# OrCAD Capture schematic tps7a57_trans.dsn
size A; title: TPS7A57 5-A, Low-VIN Ultra-Low Dropout Voltage Regulator; rev: 1.0
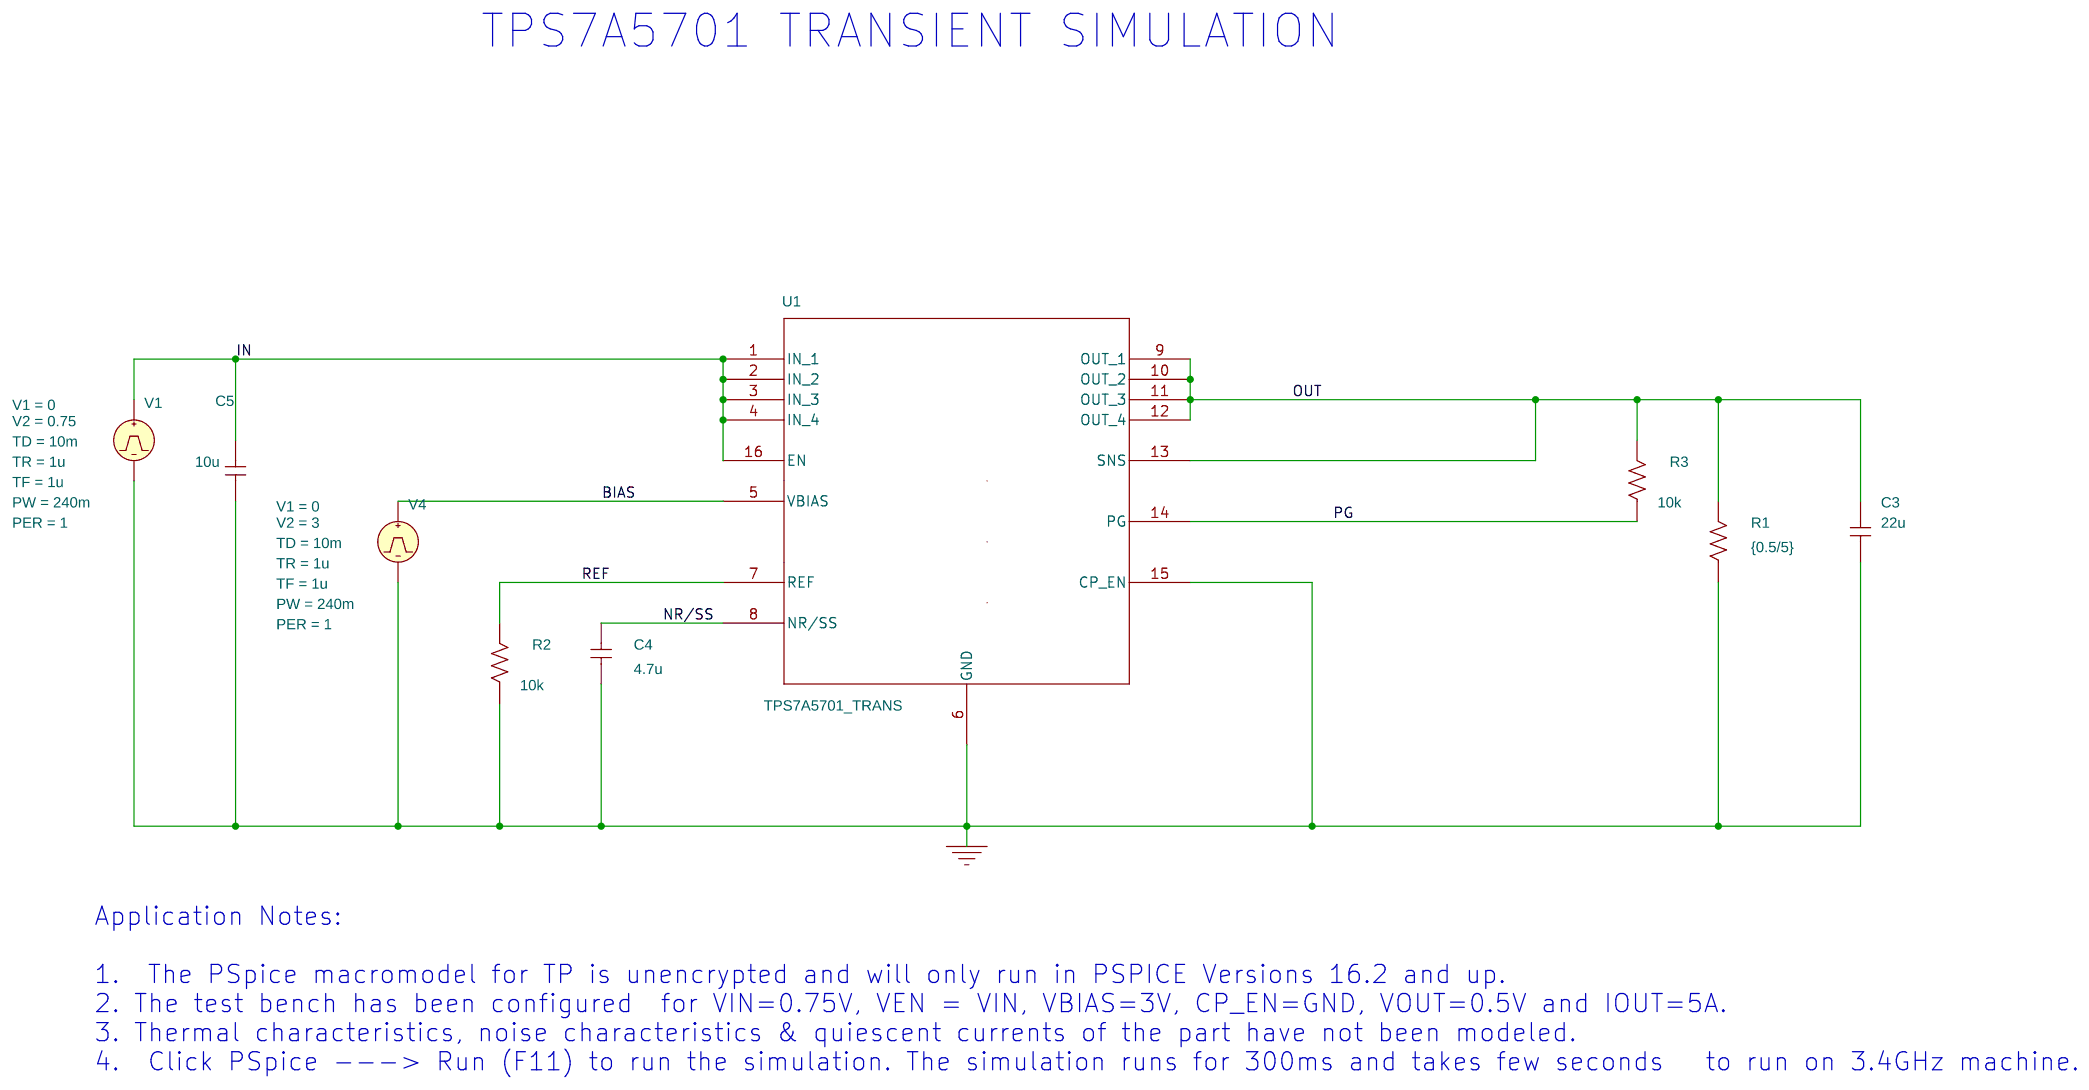
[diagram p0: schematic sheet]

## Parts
C3  22u  [RAD/CK05]
C4  4.7u  [RAD/CK05]
C5  10u  [RAD/CK05]
R1  {0.5/5}  [AX/RC05]
R2  10k  [AX/RC05]
R3  10k  [AX/RC05]
U1  TPS7A5701_TRANS  [RTE0016C]
V1  VPULSE
V4  VPULSE

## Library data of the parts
C3-C5 = C
R1-R3 = R
U1 = TPS7A5701_TRANS
V1 = VPULSE: PER: 1; PW: 240m; TD: 10m; TF: 1u; TR: 1u; V1: 0; V2: 0.75
V4 = VPULSE: PER: 1; PW: 240m; TD: 10m; TF: 1u; TR: 1u; V1: 0; V2: 3

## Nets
0: C3.1 C4.1 C5.1 R1.1 R2.1 U1.6(GND) U1.15(CP_EN) V1.2(-) V4.2(-)
BIAS: U1.5(VBIAS) V4.1(+)
IN: C5.2 U1.1(IN) U1.2(IN) U1.3(IN) U1.4(IN) U1.16(EN) V1.1(+)
NR/SS: C4.2 U1.8(NR/SS)
OUT: C3.2 R1.2 R3.2 U1.9(OUT_1) U1.10(OUT_2) U1.11(OUT_3) U1.12(OUT_4) U1.13(SNS)
PG: R3.1 U1.14(PG)
REF: R2.2 U1.7(REF)

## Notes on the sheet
- TPS7A5701 TRANSIENT SIMULATION
- Application Notes:
  1.  The PSpice macromodel for TP is unencrypted and will only run in PSPICE Versions 16.2 and up.
  2. The test bench has been configured  for VIN=0.75V, VEN = VIN, VBIAS=3V, CP_EN=GND, VOUT=0.5V and IOUT=5A.
  3. Thermal characteristics, noise characteristics & quiescent currents of the part have not been modeled.
  4.  Click PSpice ---> Run (F11) to run the simulation. The simulation runs for 300ms and takes few seconds   to run on 3.4GHz machine.
